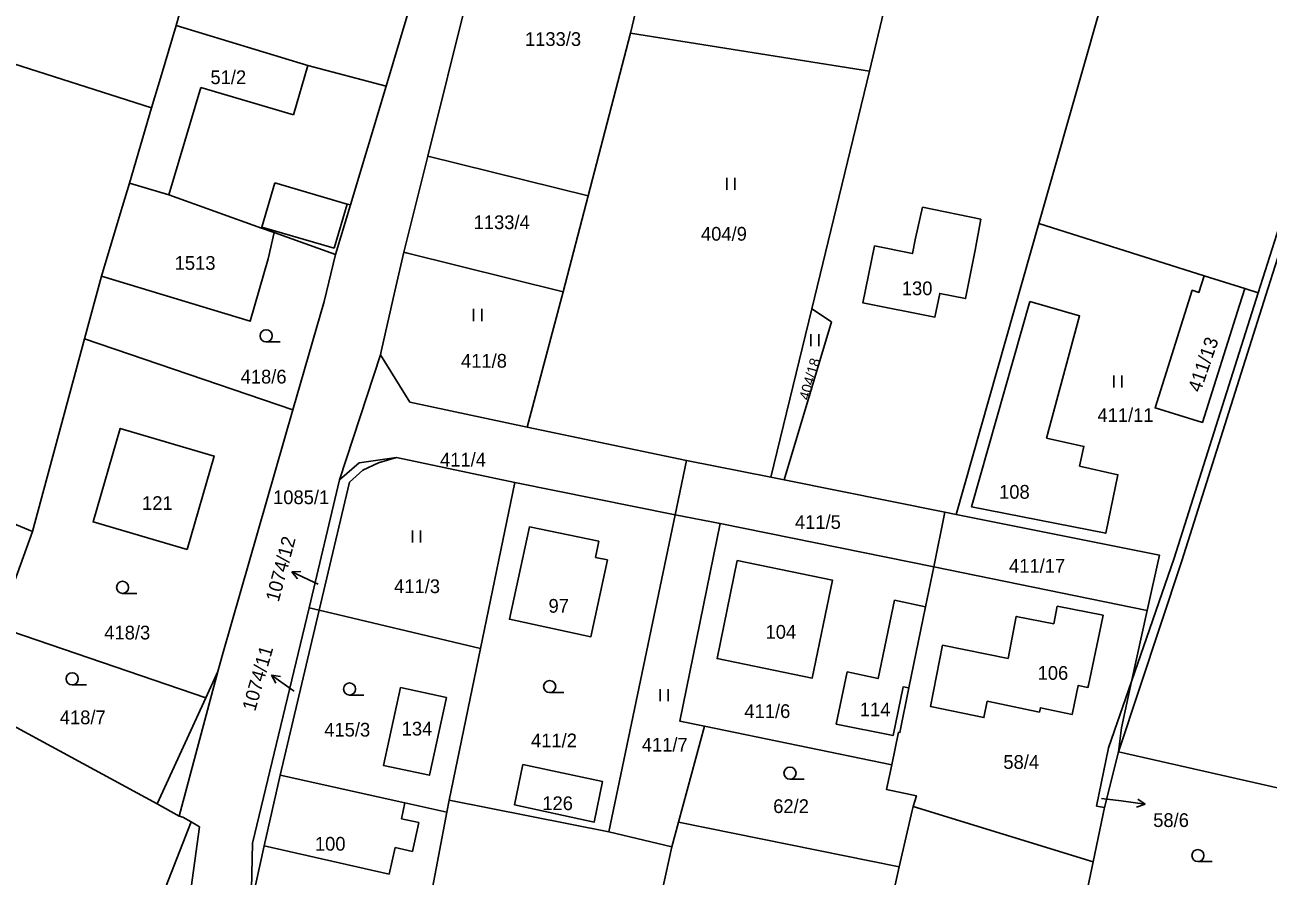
# Model space of a CAD drawing. Extents: x -746176 to -739709, y -1128407 to -1124482.
# Drawn here: x -742377 to -742223, y -1125966 to -1125860.6 of the extents above; entities that cross this region are included whole.
import ezdxf

# ---------------------------------------------------------------- set-up
doc = ezdxf.new("R2010")
doc.units = 0
for name, color, linetype in [('Vrstva 33', 7, 'Continuous'), ('Vrstva 42', 7, 'Continuous'), ('Vrstva 43', 7, 'Continuous'), ('Vrstva 44', 7, 'Continuous'), ('Vrstva 47', 7, 'Continuous')]:
    doc.layers.add(name, color=color, linetype=linetype)

msp = doc.modelspace()

# ---------------------------------------------------------------- linework, layer by layer
at = {"layer": 'Vrstva 33'}
for p, q in [((-742297.47, -1125842.97), (-742301.95, -1125861.59)), ((-742326.59, -1125849.41), (-742332.22, -1125868.16)), ((-742327.06, -1125876.83), (-742320.67, -1125851.28)), ((-742361.26, -1125870.87), (-742391.8, -1125861.15)), ((-742301.95, -1125861.59), (-742307.2, -1125881.77)), ((-742272.35, -1125866.33), (-742301.95, -1125861.59)), ((-742279.49, -1125895.76), (-742272.35, -1125866.33)), ((-742361.26, -1125870.87), (-742364, -1125880.2)), ((-742330.04, -1125888.75), (-742327.06, -1125876.83)), ((-742327.06, -1125876.83), (-742307.2, -1125881.77)), ((-742307.2, -1125881.77), (-742310.3, -1125893.66)), ((-742265.76, -1125883.17), (-742258.57, -1125884.66)), ((-742261.6, -1125921.22), (-742251.35, -1125885.17)), ((-742251.35, -1125885.17), (-742230.88, -1125891.65)), ((-742346.08, -1125886.31), (-742338.49, -1125889.03)), ((-742367.46, -1125891.72), (-742369.56, -1125899.45)), ((-742230.88, -1125891.65), (-742225.86, -1125893.24)), ((-742225.86, -1125893.24), (-742224.19, -1125893.77)), ((-742284.56, -1125916.62), (-742279.49, -1125895.76)), ((-742369.56, -1125899.45), (-742376.04, -1125923.32)), ((-742343.77, -1125908.28), (-742369.56, -1125899.45)), ((-742337.98, -1125916.93), (-742332.93, -1125901.45)), ((-742314.74, -1125910.42), (-742295.02, -1125914.52)), ((-742316.28, -1125917.27), (-742330.95, -1125914.18)), ((-742296.43, -1125921.26), (-742295.02, -1125914.52)), ((-742295.02, -1125914.52), (-742284.56, -1125916.62)), ((-742341.73, -1125932.77), (-742337.98, -1125916.93)), ((-742316.28, -1125917.27), (-742320.52, -1125937.81)), ((-742296.43, -1125921.26), (-742316.28, -1125917.27)), ((-742282.91, -1125916.95), (-742284.56, -1125916.62)), ((-742282.91, -1125916.95), (-742263.01, -1125920.94)), ((-742304.63, -1125960.54), (-742296.43, -1125921.26)), ((-742296.43, -1125921.26), (-742290.84, -1125922.32)), ((-742290.84, -1125922.32), (-742264.39, -1125927.72)), ((-742264.39, -1125927.72), (-742263.01, -1125920.94)), ((-742263.01, -1125920.94), (-742261.6, -1125921.22)), ((-742380.33, -1125935.12), (-742376.04, -1125923.32)), ((-742264.39, -1125927.72), (-742265.4, -1125932.68)), ((-742237.93, -1125933.1), (-742264.39, -1125927.72)), ((-742340.51, -1125933.06), (-742345.34, -1125953.5)), ((-742340.51, -1125933.06), (-742341.73, -1125932.77)), ((-742340.51, -1125933.06), (-742320.52, -1125937.81)), ((-742267.46, -1125942.71), (-742265.4, -1125932.68)), ((-742239.87, -1125941.89), (-742237.93, -1125933.1)), ((-742354.55, -1125943.93), (-742380.33, -1125935.12)), ((-742320.52, -1125937.81), (-742324.4, -1125956.6)), ((-742353.05, -1125940.67), (-742354.55, -1125943.93)), ((-742360.59, -1125957.08), (-742383.73, -1125944.51)), ((-742360.59, -1125957.08), (-742354.55, -1125943.93)), ((-742292.77, -1125947.44), (-742295.99, -1125959.35)), ((-742269.58, -1125952.24), (-742292.77, -1125947.44)), ((-742241.51, -1125950.63), (-742243.24, -1125957.53)), ((-742215.07, -1125956.62), (-742241.51, -1125950.63)), ((-742324.4, -1125956.6), (-742324.69, -1125958.1)), ((-742304.63, -1125960.54), (-742324.4, -1125956.6)), ((-742266.93, -1125957.38), (-742244.64, -1125964.23)), ((-742243.24, -1125957.53), (-742244.64, -1125964.23)), ((-742243.24, -1125957.53), (-742244.22, -1125957.34)), ((-742296.81, -1125962.38), (-742304.63, -1125960.54)), ((-742295.99, -1125959.35), (-742296.81, -1125962.38)), ((-742268.65, -1125964.88), (-742295.99, -1125959.35)), ((-742296.81, -1125962.38), (-742300.78, -1125980.44)), ((-742244.64, -1125964.23), (-742246.75, -1125974.33))]:
    msp.add_line(p, q, dxfattribs=at)
for points in [[(-742257.65, -1125810.78), (-742268.09, -1125852.98), (-742269.07, -1125852.77), (-742269.89, -1125856.16), (-742270.81, -1125859.92), (-742272.35, -1125866.33)], [(-742251.35, -1125885.17), (-742245.39, -1125864.19), (-742231.78, -1125816.3)], [(-742224.19, -1125893.77), (-742219.86, -1125880.14), (-742206.44, -1125820.89)], [(-742353.96, -1125840.78), (-742358.42, -1125859.19), (-742357.84, -1125859.34), (-742358.23, -1125860.65)], [(-742358.23, -1125860.65), (-742360.05, -1125866.75), (-742361.26, -1125870.87)], [(-742332.22, -1125868.16), (-742341.91, -1125865.6), (-742358.23, -1125860.65)], [(-742332.22, -1125868.16), (-742336.64, -1125882.89), (-742338.49, -1125889.03)], [(-742241.51, -1125950.63), (-742233.66, -1125926.96), (-742223.23, -1125894.07), (-742218.91, -1125880.44), (-742217.69, -1125875.07), (-742216.33, -1125869.06)], [(-742367.46, -1125891.72), (-742365.16, -1125884), (-742364, -1125880.2)], [(-742364, -1125880.2), (-742359.13, -1125881.64), (-742347.65, -1125885.75), (-742346.08, -1125886.31)], [(-742258.57, -1125884.66), (-742259.27, -1125888.5), (-742260.46, -1125894.48), (-742263.65, -1125893.85), (-742264.23, -1125896.78), (-742273.15, -1125895.02), (-742271.72, -1125887.95), (-742267.02, -1125888.9), (-742266.64, -1125887), (-742265.76, -1125883.17)], [(-742346.08, -1125886.31), (-742346.82, -1125889.56), (-742349.06, -1125897.29), (-742367.46, -1125891.72)], [(-742338.49, -1125889.03), (-742339.9, -1125894.84), (-742343.77, -1125908.28)], [(-742332.93, -1125901.45), (-742332.83, -1125901.02), (-742331.14, -1125893.58), (-742330.04, -1125888.75)], [(-742310.3, -1125893.66), (-742329.73, -1125888.83), (-742330.04, -1125888.75)], [(-742225.86, -1125893.24), (-742226.52, -1125895.3), (-742231.11, -1125909.81), (-742236.97, -1125908.02), (-742232.36, -1125893.45), (-742231.54, -1125893.71), (-742230.88, -1125891.65)], [(-742310.3, -1125893.66), (-742314.57, -1125909.78), (-742314.74, -1125910.42)], [(-742239.87, -1125941.89), (-742234.61, -1125926.63), (-742224.19, -1125893.77)], [(-742279.49, -1125895.76), (-742277.04, -1125897.38), (-742282.91, -1125916.95)], [(-742252.47, -1125894.85), (-742259.69, -1125920.29), (-742243.08, -1125923.55), (-742241.58, -1125916.3), (-742246.33, -1125915.23), (-742245.79, -1125912.79), (-742250.41, -1125911.75), (-742246.32, -1125896.62), (-742252.47, -1125894.85)], [(-742314.74, -1125910.42), (-742329.26, -1125907.3), (-742332.93, -1125901.45)], [(-742343.77, -1125908.28), (-742352.46, -1125938.44), (-742353.05, -1125940.67)], [(-742356.87, -1125925.57), (-742368.52, -1125922.14), (-742365.15, -1125910.57), (-742353.51, -1125913.99), (-742356.87, -1125925.57)], [(-742376.04, -1125923.32), (-742388.87, -1125917.99), (-742404.91, -1125911.78)], [(-742330.95, -1125914.18), (-742333.17, -1125914.81), (-742335.12, -1125915.74), (-742336.77, -1125917.22), (-742340.51, -1125933.06)], [(-742337.98, -1125916.93), (-742335.56, -1125914.84), (-742330.95, -1125914.18)], [(-742290.84, -1125922.32), (-742295.85, -1125946.81), (-742292.77, -1125947.44)], [(-742261.6, -1125921.22), (-742236.44, -1125926.26), (-742237.93, -1125933.1)], [(-742305.85, -1125924.52), (-742314.47, -1125922.77), (-742316.95, -1125934.19), (-742306.85, -1125936.36), (-742304.8, -1125926.85), (-742306.27, -1125926.55), (-742305.85, -1125924.52)], [(-742288.73, -1125926.94), (-742291.23, -1125939.08), (-742279.43, -1125941.49), (-742276.92, -1125929.36), (-742288.73, -1125926.94)], [(-742348.95, -1125969.57), (-742348.77, -1125961.93), (-742341.73, -1125932.77)], [(-742265.4, -1125932.68), (-742269.24, -1125931.85), (-742271.28, -1125941.54), (-742275.1, -1125940.73), (-742276.46, -1125947.18), (-742269.43, -1125948.6), (-742268.18, -1125942.58), (-742267.46, -1125942.71)], [(-742249.09, -1125932.57), (-742249.52, -1125934.75), (-742254.17, -1125933.84), (-742255.18, -1125939.05), (-742263.28, -1125937.42), (-742264.8, -1125945), (-742258.18, -1125946.38), (-742257.75, -1125944.36), (-742251.29, -1125945.7), (-742251.18, -1125945.16), (-742247.23, -1125945.98), (-742246.48, -1125942.4), (-742245.29, -1125942.65), (-742245.23, -1125942.35), (-742243.85, -1125935.89), (-742243.41, -1125933.71), (-742249.09, -1125932.57)], [(-742244.22, -1125957.34), (-742242.72, -1125950.14), (-742239.87, -1125941.89)], [(-742241.51, -1125950.63), (-742241.14, -1125947.64), (-742239.87, -1125941.89)], [(-742324.73, -1125943.91), (-742326.85, -1125953.53), (-742332.56, -1125952.31), (-742330.42, -1125942.66), (-742324.73, -1125943.91)], [(-742267.46, -1125942.71), (-742268.58, -1125948.23), (-742268.73, -1125948.2), (-742269.58, -1125952.24)], [(-742315.28, -1125952.17), (-742305.42, -1125954.28), (-742306.43, -1125959.32), (-742316.33, -1125957.18), (-742315.28, -1125952.17)], [(-742269.58, -1125952.24), (-742270.22, -1125955.3), (-742266.54, -1125956.05), (-742266.93, -1125957.38)], [(-742345.34, -1125953.5), (-742347.31, -1125962.26), (-742348.95, -1125969.57)], [(-742324.69, -1125958.1), (-742329.9, -1125956.94), (-742345.34, -1125953.5)], [(-742357.41, -1125958.73), (-742357.86, -1125958.57), (-742360.59, -1125957.08)], [(-742268.65, -1125964.88), (-742267.07, -1125957.87), (-742266.93, -1125957.38)], [(-742365.43, -1125982.55), (-742356.37, -1125959.31), (-742357.41, -1125958.73)], [(-742327.47, -1125972.62), (-742326.77, -1125969.01), (-742324.69, -1125958.1)], [(-742269.67, -1125969.51), (-742269.48, -1125968.58), (-742268.65, -1125964.88)]]:
    msp.add_lwpolyline(points, dxfattribs=at)
at = {"layer": 'Vrstva 43'}
for p, q in [((-742343.89, -1125928.33), (-742342.77, -1125928.3)), ((-742341.17, -1125929.6), (-742343.89, -1125928.33)), ((-742343.89, -1125928.33), (-742343.19, -1125929.21)), ((-742340.63, -1125929.86), (-742341.17, -1125929.6)), ((-742343.96, -1125942.86), (-742346.42, -1125941.14)), ((-742346.42, -1125941.14), (-742345.31, -1125941.3)), ((-742346.42, -1125941.14), (-742345.89, -1125942.12)), ((-742343.6, -1125943.11), (-742343.96, -1125942.86)), ((-742243.59, -1125956.38), (-742241.17, -1125956.7)), ((-742241.17, -1125956.7), (-742238.2, -1125957.12)), ((-742238.2, -1125957.12), (-742239.26, -1125957.47)), ((-742238.2, -1125957.12), (-742239.12, -1125956.48))]:
    msp.add_line(p, q, dxfattribs=at)
at = {"layer": 'Vrstva 44'}
for p, q in [((-742290.02, -1125881.03), (-742290.02, -1125879.53)), ((-742289.02, -1125881.03), (-742289.02, -1125879.53)), ((-742321.38, -1125897.26), (-742321.38, -1125895.76)), ((-742320.38, -1125897.26), (-742320.38, -1125895.76)), ((-742279.62, -1125900.39), (-742279.62, -1125898.89)), ((-742278.62, -1125900.39), (-742278.62, -1125898.89)), ((-742347.08, -1125899.85), (-742345.33, -1125899.85)), ((-742242.07, -1125905.51), (-742242.07, -1125904.01)), ((-742241.07, -1125905.51), (-742241.07, -1125904.01)), ((-742328.97, -1125924.71), (-742328.97, -1125923.21)), ((-742327.97, -1125924.71), (-742327.97, -1125923.21)), ((-742364.86, -1125931), (-742363.11, -1125931)), ((-742371.1, -1125942.32), (-742369.35, -1125942.32)), ((-742336.74, -1125943.59), (-742334.99, -1125943.59)), ((-742311.96, -1125943.29), (-742310.21, -1125943.29)), ((-742298.29, -1125944.34), (-742298.29, -1125942.84)), ((-742297.29, -1125944.34), (-742297.29, -1125942.84)), ((-742282.19, -1125954.01), (-742280.44, -1125954.01)), ((-742231.66, -1125964.22), (-742229.91, -1125964.22))]:
    msp.add_line(p, q, dxfattribs=at)
for centre in [(-742347.08, -1125899.1), (-742364.86, -1125930.25), (-742371.1, -1125941.57), (-742336.74, -1125942.84), (-742311.96, -1125942.54), (-742282.19, -1125953.26), (-742231.66, -1125963.47)]:
    msp.add_circle(centre, 0.75, dxfattribs=at)
at = {"layer": 'Vrstva 47'}
for p, q in [((-742343.69, -1125871.72), (-742341.91, -1125865.6)), ((-742359.13, -1125881.64), (-742355.15, -1125868.33)), ((-742355.15, -1125868.33), (-742343.69, -1125871.72)), ((-742347.62, -1125885.65), (-742346, -1125880.14)), ((-742346, -1125880.14), (-742337.04, -1125882.77)), ((-742338.65, -1125888.24), (-742337.04, -1125882.77)), ((-742337.04, -1125882.77), (-742336.64, -1125882.89)), ((-742347.65, -1125885.75), (-742347.62, -1125885.65)), ((-742347.62, -1125885.65), (-742338.65, -1125888.24)), ((-742357.86, -1125958.57), (-742353.05, -1125940.67)), ((-742330.33, -1125958.91), (-742329.9, -1125956.94)), ((-742356.37, -1125959.31), (-742355.32, -1125959.9)), ((-742330.33, -1125958.91), (-742328.18, -1125959.38)), ((-742357.49, -1125975.36), (-742355.32, -1125959.9)), ((-742328.97, -1125962.95), (-742328.18, -1125959.38)), ((-742347.31, -1125962.26), (-742331.83, -1125965.77)), ((-742331.83, -1125965.77), (-742331.11, -1125962.48)), ((-742331.11, -1125962.48), (-742328.97, -1125962.95))]:
    msp.add_line(p, q, dxfattribs=at)

# ---------------------------------------------------------------- texts
at = {"layer": 'Vrstva 42'}
for s, p in [('1133/3', (-742315.02, -1125863.19)), ('51/2', (-742353.98, -1125867.92)), ('1133/4', (-742321.38, -1125885.88)), ('404/9', (-742293.22, -1125887.31)), ('1513', (-742358.41, -1125890.92)), ('130', (-742268.34, -1125894.06)), ('411/8', (-742322.94, -1125903.04)), ('418/6', (-742350.24, -1125905)), ('411/11', (-742244.11, -1125909.76)), ('411/4', (-742325.54, -1125915.28)), ('108', (-742256.29, -1125919.27)), ('121', (-742362.45, -1125920.66)), ('1085/1', (-742346.22, -1125919.94)), ('411/5', (-742281.58, -1125923.01)), ('411/17', (-742255.06, -1125928.43)), ('411/3', (-742331.23, -1125930.96)), ('97', (-742312.1, -1125933.39)), ('418/3', (-742367.13, -1125936.7)), ('104', (-742285.22, -1125936.61)), ('106', (-742251.52, -1125941.7)), ('418/7', (-742372.64, -1125947.2)), ('411/6', (-742287.84, -1125946.43)), ('114', (-742273.54, -1125946.22)), ('415/3', (-742339.88, -1125948.73)), ('134', (-742330.29, -1125948.6)), ('411/2', (-742314.27, -1125950.06)), ('411/7', (-742300.55, -1125950.59)), ('58/4', (-742255.76, -1125952.73)), ('126', (-742312.87, -1125957.84)), ('62/2', (-742284.27, -1125958.2)), ('58/6', (-742237.2, -1125959.93)), ('100', (-742341.04, -1125962.86))]:
    msp.add_text(s, height=1.7, dxfattribs=at).set_placement(p)
for s, height, rotation, p in [('411/13', 1.7, 71, (-742231.34, -1125906.2)), ('404/18', 1.288, 74, (-742279.85, -1125907.15)), ('1074/12', 1.7, 75, (-742345.53, -1125932.15)), ('1074/11', 1.7, 74, (-742348.44, -1125945.68))]:
    msp.add_text(s, height=height, rotation=rotation, dxfattribs=at).set_placement(p)

doc.saveas('drawing.dxf')
